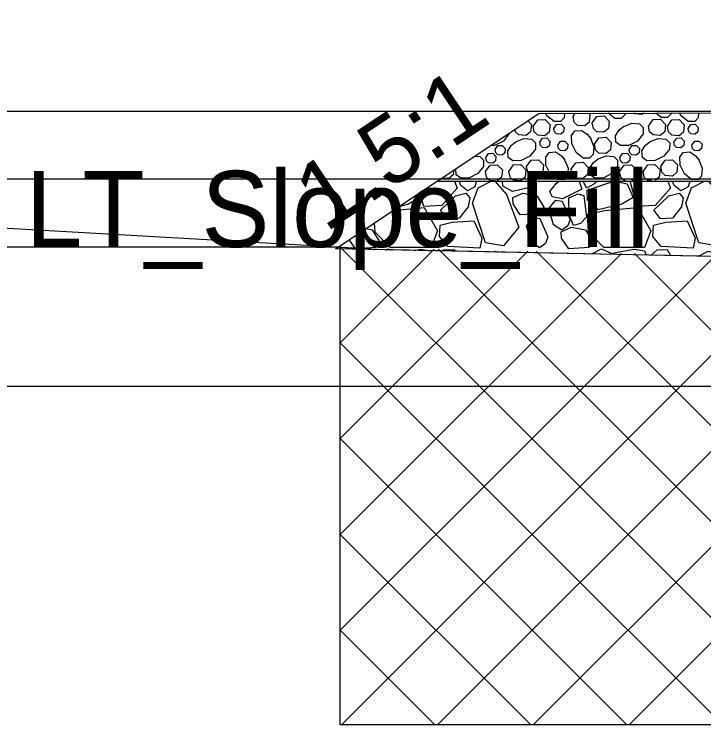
# Model space of a CAD drawing. Extents: x -14026 to 1303, y -10 to 9533.
# Drawn here: x 108.35 to 118.52, y 4495 to 4505.49 of the extents above; entities that cross this region are included whole.
import ezdxf

# ---------------------------------------------------------------- set-up
doc = ezdxf.new("R2010")
doc.units = 0
for name, color, linetype in [('Exist Cross Section Cell', 7, 'Continuous'), ('Exist XS Ground Line', 7, 'Continuous'), ('Old_Level_10', 7, 'Continuous'), ('Prop XS Side Slope Text', 7, 'Continuous'), ('Scratch_Level_0', 7, 'Continuous'), ('Scratch_Level_3', 7, 'Continuous'), ('Scratch_Level_5', 7, 'Continuous')]:
    doc.layers.add(name, color=color, linetype=linetype)

msp = doc.modelspace()

# ---------------------------------------------------------------- linework, layer by layer
at = {"layer": 'Exist Cross Section Cell'}
msp.add_line((0, 4500), (150, 4500), dxfattribs=at)
at = {"layer": 'Exist XS Ground Line'}
msp.add_lwpolyline([(80.783, 4502.722), (92.291, 4502.548), (100.78, 4502.619), (103.84, 4502.584), (113.704, 4502.022), (124.315, 4501.802), (127.541, 4505.019), (127.873, 4505.327), (129.154, 4505.491)], dxfattribs=at)
at = {"layer": 'Old_Level_10'}
for p, q in [((116.592, 4503.981), (116.625, 4504.029)), ((114.586, 4503.027), (125.544, 4503.027)), ((114.306, 4502.84), (114.33, 4502.784)), ((116.618, 4501.961), (116.62, 4501.956)), ((118.02, 4501.949), (118.019, 4501.928))]:
    msp.add_line(p, q, dxfattribs=at)
msp.add_lwpolyline([(113.086, 4502.027), (116.086, 4504.027), (126.573, 4504.053), (124.315, 4501.802)], close=True, dxfattribs=at)
for points in [[(116.465, 4504.028), (116.459, 4503.96), (116.407, 4503.905), (116.313, 4503.907), (116.207, 4503.99), (116.188, 4504.028)], [(116.818, 4504.029), (116.841, 4504.006), (116.83, 4503.897), (116.764, 4503.842), (116.658, 4503.85), (116.608, 4503.898), (116.592, 4503.981)], [(117.359, 4504.031), (117.356, 4504.005), (117.304, 4503.95), (117.21, 4503.952), (117.11, 4504.03)], [(117.633, 4504.031), (117.609, 4504.012), (117.503, 4504.019), (117.491, 4504.031)], [(118.041, 4504.032), (118.04, 4504.021), (117.987, 4503.966), (117.894, 4503.968), (117.812, 4504.032)], [(118.444, 4504.033), (118.438, 4503.96), (118.386, 4503.905), (118.292, 4503.907), (118.186, 4503.99), (118.164, 4504.033)], [(115.923, 4503.919), (115.977, 4503.863), (115.966, 4503.755), (115.9, 4503.7), (115.794, 4503.708), (115.744, 4503.756), (115.736, 4503.794)], [(116.033, 4503.992), (116.009, 4503.966), (115.995, 4503.966)], [(116.004, 4503.835), (116.071, 4503.931), (116.179, 4503.937), (116.253, 4503.859), (116.242, 4503.751), (116.176, 4503.696), (116.07, 4503.704), (116.02, 4503.752), (116.004, 4503.835)], [(116.876, 4503.886), (116.943, 4503.982), (117.05, 4503.988), (117.125, 4503.911), (117.114, 4503.802), (117.048, 4503.747), (116.942, 4503.755), (116.892, 4503.803), (116.876, 4503.886)], [(117.706, 4503.839), (117.773, 4503.935), (117.881, 4503.941), (117.955, 4503.863), (117.945, 4503.755), (117.878, 4503.7), (117.772, 4503.708), (117.722, 4503.756), (117.706, 4503.839)], [(117.983, 4503.835), (118.05, 4503.931), (118.157, 4503.937), (118.232, 4503.859), (118.221, 4503.751), (118.155, 4503.696), (118.049, 4503.704), (117.999, 4503.752), (117.983, 4503.835)], [(116.31, 4503.805), (116.35, 4503.863), (116.415, 4503.867), (116.459, 4503.82), (116.453, 4503.755), (116.413, 4503.722), (116.35, 4503.727), (116.32, 4503.756), (116.31, 4503.805)], [(117.331, 4503.83), (117.457, 4503.88), (117.572, 4503.87), (117.627, 4503.818), (117.626, 4503.724), (117.542, 4503.618), (117.414, 4503.553), (117.292, 4503.551), (117.224, 4503.6), (117.217, 4503.696), (117.273, 4503.783), (117.336, 4503.834)], [(118.289, 4503.805), (118.329, 4503.863), (118.393, 4503.867), (118.438, 4503.82), (118.432, 4503.755), (118.392, 4503.722), (118.328, 4503.727), (118.298, 4503.756), (118.289, 4503.805)], [(115.647, 4503.735), (115.647, 4503.724), (115.564, 4503.618), (115.435, 4503.553), (115.374, 4503.552)], [(116.849, 4503.66), (116.899, 4503.535), (116.889, 4503.419), (116.836, 4503.364), (116.743, 4503.366), (116.636, 4503.449), (116.572, 4503.578), (116.57, 4503.699), (116.618, 4503.768), (116.715, 4503.774), (116.801, 4503.719), (116.852, 4503.655)], [(115.743, 4503.606), (115.868, 4503.655), (115.984, 4503.646), (116.039, 4503.593), (116.037, 4503.5), (115.954, 4503.393), (115.825, 4503.329), (115.704, 4503.327), (115.635, 4503.375), (115.629, 4503.472), (115.684, 4503.558), (115.748, 4503.609)], [(116.102, 4503.604), (116.142, 4503.661), (116.207, 4503.665), (116.251, 4503.618), (116.245, 4503.553), (116.205, 4503.52), (116.142, 4503.525), (116.112, 4503.554), (116.102, 4503.604)], [(116.367, 4503.556), (116.407, 4503.614), (116.471, 4503.617), (116.516, 4503.571), (116.51, 4503.506), (116.47, 4503.473), (116.406, 4503.478), (116.376, 4503.507), (116.367, 4503.556)], [(116.906, 4503.572), (116.973, 4503.667), (117.08, 4503.674), (117.155, 4503.596), (117.144, 4503.488), (117.078, 4503.433), (116.972, 4503.44), (116.922, 4503.489), (116.906, 4503.572)], [(117.721, 4503.606), (117.847, 4503.655), (117.963, 4503.646), (118.018, 4503.593), (118.016, 4503.5), (117.933, 4503.393), (117.804, 4503.329), (117.682, 4503.327), (117.614, 4503.375), (117.608, 4503.472), (117.663, 4503.558), (117.726, 4503.609)], [(118.081, 4503.604), (118.121, 4503.661), (118.185, 4503.665), (118.23, 4503.618), (118.224, 4503.553), (118.184, 4503.52), (118.12, 4503.525), (118.09, 4503.554), (118.081, 4503.604)], [(118.345, 4503.556), (118.386, 4503.614), (118.45, 4503.617), (118.495, 4503.571), (118.488, 4503.506), (118.449, 4503.473), (118.385, 4503.478), (118.355, 4503.507), (118.345, 4503.556)], [(115.443, 4503.493), (115.483, 4503.551), (115.548, 4503.554), (115.593, 4503.508), (115.586, 4503.443), (115.546, 4503.41), (115.483, 4503.414), (115.453, 4503.443), (115.443, 4503.493)], [(117.422, 4503.493), (117.462, 4503.551), (117.526, 4503.554), (117.571, 4503.508), (117.565, 4503.443), (117.525, 4503.41), (117.461, 4503.414), (117.431, 4503.443), (117.422, 4503.493)], [(115.139, 4503.396), (115.215, 4503.389), (115.27, 4503.337), (115.269, 4503.243), (115.185, 4503.137), (115.056, 4503.072), (114.935, 4503.07), (114.867, 4503.119), (114.861, 4503.21)], [(115.304, 4503.377), (115.345, 4503.434), (115.409, 4503.438), (115.454, 4503.391), (115.447, 4503.326), (115.408, 4503.293), (115.344, 4503.298), (115.314, 4503.327), (115.304, 4503.377)], [(116.468, 4503.343), (116.518, 4503.217), (116.508, 4503.102), (116.456, 4503.047), (116.362, 4503.049), (116.256, 4503.132), (116.191, 4503.261), (116.189, 4503.382), (116.238, 4503.45), (116.334, 4503.457), (116.421, 4503.402), (116.471, 4503.338)], [(116.953, 4503.349), (117.079, 4503.399), (117.194, 4503.389), (117.249, 4503.337), (117.247, 4503.243), (117.164, 4503.137), (117.035, 4503.072), (116.914, 4503.07), (116.845, 4503.119), (116.839, 4503.216), (116.894, 4503.302), (116.958, 4503.353)], [(117.283, 4503.377), (117.323, 4503.434), (117.388, 4503.438), (117.433, 4503.391), (117.426, 4503.326), (117.386, 4503.293), (117.323, 4503.298), (117.293, 4503.327), (117.283, 4503.377)], [(118.447, 4503.343), (118.497, 4503.217), (118.487, 4503.102), (118.435, 4503.047), (118.341, 4503.049), (118.234, 4503.132), (118.17, 4503.261), (118.168, 4503.382), (118.216, 4503.45), (118.313, 4503.457), (118.4, 4503.402), (118.45, 4503.338)], [(115.3, 4503.167), (115.367, 4503.262), (115.474, 4503.268), (115.549, 4503.191), (115.538, 4503.083), (115.474, 4503.029)], [(115.647, 4503.17), (115.714, 4503.266), (115.821, 4503.272), (115.896, 4503.195), (115.885, 4503.086), (115.819, 4503.031), (115.713, 4503.039), (115.663, 4503.087), (115.647, 4503.17)], [(115.907, 4503.241), (115.975, 4503.336), (116.082, 4503.342), (116.157, 4503.265), (116.146, 4503.157), (116.079, 4503.101), (115.973, 4503.109), (115.924, 4503.158), (115.907, 4503.241)], [(116.565, 4503.202), (116.632, 4503.298), (116.74, 4503.304), (116.814, 4503.226), (116.804, 4503.118), (116.737, 4503.063), (116.631, 4503.071), (116.581, 4503.119), (116.565, 4503.202)], [(117.279, 4503.167), (117.346, 4503.262), (117.453, 4503.268), (117.528, 4503.191), (117.517, 4503.083), (117.459, 4503.034)], [(117.625, 4503.17), (117.693, 4503.266), (117.8, 4503.272), (117.875, 4503.195), (117.864, 4503.086), (117.802, 4503.035)], [(117.886, 4503.241), (117.953, 4503.336), (118.061, 4503.342), (118.135, 4503.265), (118.124, 4503.157), (118.058, 4503.101), (117.952, 4503.109), (117.902, 4503.158), (117.886, 4503.241)], [(114.832, 4503.191), (114.825, 4503.118), (114.758, 4503.063), (114.652, 4503.071), (114.652, 4503.071)], [(115.444, 4503.029), (115.366, 4503.035), (115.316, 4503.083), (115.3, 4503.167)], [(117.36, 4503.034), (117.345, 4503.035), (117.295, 4503.083), (117.279, 4503.167)], [(117.749, 4503.035), (117.691, 4503.039), (117.642, 4503.087), (117.625, 4503.17)], [(114.843, 4503.027), (114.882, 4502.921), (114.655, 4502.667), (114.393, 4502.65), (114.333, 4502.859)], [(115.033, 4502.883), (114.936, 4502.96), (114.911, 4503.027)], [(115.167, 4503.027), (115.143, 4502.944), (115.033, 4502.883)], [(115.444, 4503.021), (115.608, 4502.827), (115.79, 4502.347), (115.564, 4502.069), (115.299, 4502.114), (115.107, 4502.701), (115.191, 4502.929), (115.382, 4503.027)], [(116.026, 4503.027), (115.915, 4502.924), (115.698, 4502.871), (115.557, 4502.953), (115.551, 4503.027)], [(116.248, 4502.875), (116.349, 4502.997), (116.388, 4503.027)], [(116.682, 4503.027), (116.722, 4502.906), (116.435, 4502.764), (116.284, 4502.794), (116.248, 4502.875)], [(116.788, 4502.923), (116.747, 4503.015), (116.741, 4503.027)], [(116.951, 4503.027), (116.899, 4502.983), (116.788, 4502.923)], [(117.478, 4502.784), (117.313, 4502.684), (116.96, 4502.601), (116.804, 4502.744), (116.798, 4502.894), (117.193, 4503.027)], [(117.208, 4503.027), (117.389, 4502.987), (117.478, 4502.784)], [(117.991, 4503.027), (118.03, 4502.921), (117.803, 4502.667), (117.54, 4502.65), (117.433, 4503.027)], [(118.18, 4502.883), (118.083, 4502.96), (118.058, 4503.027)], [(118.314, 4503.027), (118.29, 4502.944), (118.18, 4502.883)], [(118.592, 4503.021), (118.756, 4502.827), (118.938, 4502.347), (118.712, 4502.069), (118.447, 4502.114), (118.254, 4502.701), (118.339, 4502.929), (118.53, 4503.027)], [(115.07, 4502.778), (115.047, 4502.647), (114.913, 4502.478), (114.736, 4502.47), (114.638, 4502.599), (114.86, 4502.807), (115.011, 4502.851), (115.07, 4502.778)], [(115.705, 4502.785), (115.853, 4502.848), (116.061, 4502.806), (116.162, 4502.641), (116.109, 4502.545), (115.81, 4502.527), (115.709, 4502.692), (115.705, 4502.785)], [(118.218, 4502.778), (118.194, 4502.647), (118.06, 4502.478), (117.884, 4502.47), (117.786, 4502.599), (118.007, 4502.807), (118.159, 4502.851), (118.218, 4502.778)], [(114.33, 4502.784), (114.166, 4502.684), (114.019, 4502.649)], [(116.425, 4502.3), (116.303, 4502.383), (116.237, 4502.624), (116.338, 4502.747), (116.432, 4502.732), (116.55, 4502.462), (116.516, 4502.366), (116.425, 4502.3)], [(116.598, 4502.37), (116.537, 4502.524), (116.532, 4502.779), (116.665, 4502.838), (116.75, 4502.814), (116.788, 4502.492), (116.704, 4502.399), (116.598, 4502.37)], [(113.934, 4502.593), (114.398, 4502.635), (114.593, 4502.293), (114.497, 4502.045), (113.896, 4502.046), (113.674, 4502.275), (113.665, 4502.413)], [(116.805, 4502.537), (117.059, 4502.591), (117.545, 4502.635), (117.741, 4502.293), (117.644, 4502.045), (117.044, 4502.046), (116.822, 4502.275), (116.805, 4502.537)], [(114.632, 4502.376), (114.811, 4502.421), (115.13, 4502.44), (115.247, 4502.182), (115.215, 4502.037), (114.745, 4502.061), (114.62, 4502.207), (114.632, 4502.376)], [(116.095, 4502.042), (115.973, 4502.125), (115.907, 4502.366), (116.008, 4502.489), (116.103, 4502.474), (116.22, 4502.203), (116.186, 4502.108), (116.095, 4502.042)], [(117.78, 4502.376), (117.959, 4502.421), (118.277, 4502.44), (118.394, 4502.182), (118.362, 4502.037), (117.892, 4502.061), (117.768, 4502.207), (117.78, 4502.376)], [(113.533, 4502.325), (113.627, 4502.306), (113.734, 4502.142), (113.681, 4502.046), (113.382, 4502.027), (113.29, 4502.163)], [(116.419, 4502.279), (116.567, 4502.348), (116.775, 4502.306), (116.881, 4502.142), (116.829, 4502.046), (116.529, 4502.027), (116.423, 4502.186), (116.419, 4502.279)], [(113.835, 4502.012), (113.863, 4502.027), (113.899, 4502.011)], [(114.248, 4502.004), (114.346, 4502.022), (114.486, 4501.999)], [(114.663, 4501.996), (114.683, 4502.014), (114.832, 4502.016), (114.846, 4501.992)], [(116.868, 4501.951), (117.011, 4502.027), (117.164, 4501.958), (117.164, 4501.946)], [(117.198, 4501.945), (117.196, 4501.967), (117.494, 4502.022), (117.645, 4501.997), (117.677, 4501.935)], [(117.745, 4501.934), (117.831, 4502.014), (117.98, 4502.016), (118.02, 4501.949)], [(115.416, 4501.981), (115.438, 4501.992), (115.481, 4501.979)], [(118.441, 4501.92), (118.586, 4501.992), (118.757, 4501.942), (118.759, 4501.914)]]:
    msp.add_lwpolyline(points, dxfattribs=at)
at = {"layer": 'Scratch_Level_3'}
for p, q in [((126.573, 4504.053), (105.896, 4504.053)), ((125.57, 4503.053), (105.896, 4503.053)), ((113.159, 4502.053), (105.896, 4502.053))]:
    msp.add_line(p, q, dxfattribs=at)
at = {"layer": 'Scratch_Level_5'}
for p, q in [((113.159, 4502.053), (120.212, 4495)), ((113.159, 4500.639), (114.542, 4502.022)), ((114.605, 4502.021), (121.626, 4495)), ((113.159, 4499.225), (115.925, 4501.991)), ((113.159, 4497.811), (117.308, 4501.96)), ((113.159, 4496.397), (118.691, 4501.929)), ((113.176, 4495), (120.074, 4501.898)), ((116.052, 4501.988), (123.04, 4495)), ((117.499, 4501.956), (124.315, 4495.14)), ((114.59, 4495), (121.457, 4501.867)), ((116.005, 4495), (122.84, 4501.835)), ((117.419, 4495), (124.223, 4501.804)), ((113.159, 4500.639), (118.798, 4495)), ((113.159, 4499.225), (117.384, 4495)), ((113.159, 4497.811), (115.969, 4495)), ((113.159, 4496.397), (114.555, 4495))]:
    msp.add_line(p, q, dxfattribs=at)
msp.add_lwpolyline([(124.315, 4501.802), (124.315, 4495), (113.159, 4495), (113.159, 4502.053), (113.704, 4502.022)], close=True, dxfattribs=at)

# ---------------------------------------------------------------- texts
at = {"layer": 'Prop XS Side Slope Text'}
msp.add_text('1.5:1', height=1, rotation=33.6901, dxfattribs=at).set_placement((112.94, 4502.259))
at = {"layer": 'Scratch_Level_0'}
msp.add_text('LT_Slope_Fill', height=1.125, dxfattribs=at).set_placement((108.518, 4502.053))

doc.saveas('drawing.dxf')
